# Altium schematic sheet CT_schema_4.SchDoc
size 283 x 147 mm
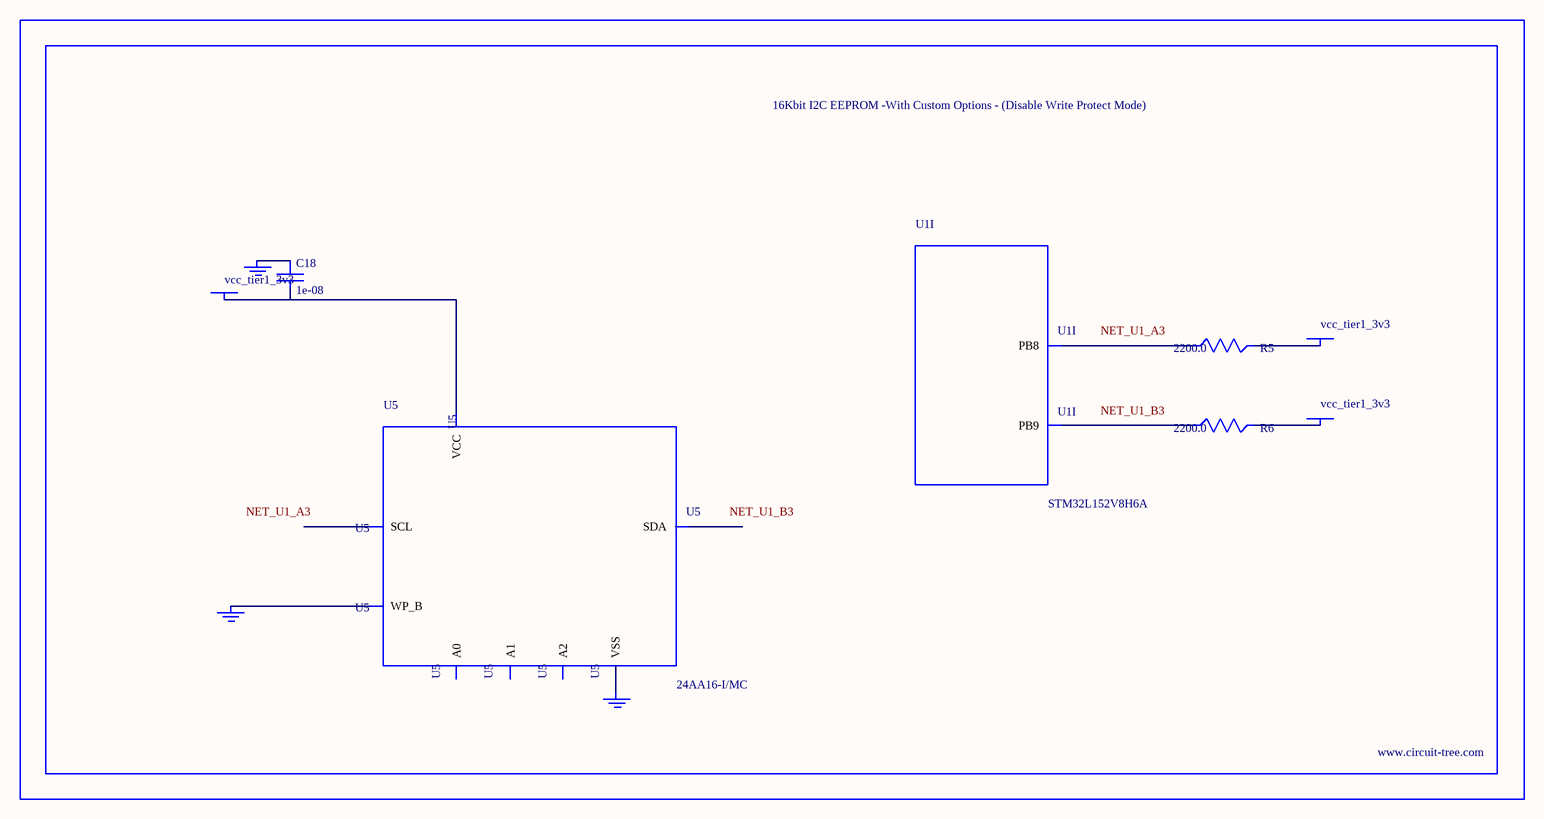
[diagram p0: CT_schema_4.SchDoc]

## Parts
BORDER3  (no value)
C18  1e-08  [C0402]
GND_INSTANCE_3_0  (no value)
GND_INSTANCE_3_1  (no value)
GND_INSTANCE_3_2  (no value)
POWER_INSTANCE_3_0  vcc_tier1_3v3
POWER_INSTANCE_3_1  vcc_tier1_3v3
POWER_INSTANCE_3_2  vcc_tier1_3v3
R5  2200.0  [R0603]
R6  2200.0  [R0603]
U1  STM32L152V8H6A  [UFBGA100]  (part I of 10)
U5  24AA16-I/MC  [TDFN-8/6MM]

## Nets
NetC18_1: C18.1 GND_INSTANCE_3_1.0(GND)
NetC18_2: C18.2 POWER_INSTANCE_3_0.0(PWR) U5.8(VCC)
NetGND_INSTANCE_3_0_0: GND_INSTANCE_3_0.0(GND) U5.7(WP_B)
NetGND_INSTANCE_3_2_0: GND_INSTANCE_3_2.0(GND) U5.4(VSS)
NetPOWER_INSTANCE_3_1_0: POWER_INSTANCE_3_1.0(PWR) R5.2
NetPOWER_INSTANCE_3_2_0: POWER_INSTANCE_3_2.0(PWR) R6.2
NetR5_1: R5.1 U1.A3(PB8)
NetR6_1: R6.1 U1.B3(PB9)

Not connected (* = marked no-connect by the designer): U5 1(A0) 2(A1) 3(A2) 5(SDA) 6(SCL)

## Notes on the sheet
- Labels drawn without touching a wire or pin: NET_U1_A3, NET_U1_B3

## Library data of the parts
BORDER3 = BORDER_PAGE3
C18 = C0402C103K3RAC
GND_INSTANCE_3_0-GND_INSTANCE_3_2 = GND
POWER_INSTANCE_3_0-POWER_INSTANCE_3_2 = PWR
R5 R6 = RC0603JR-072K2L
